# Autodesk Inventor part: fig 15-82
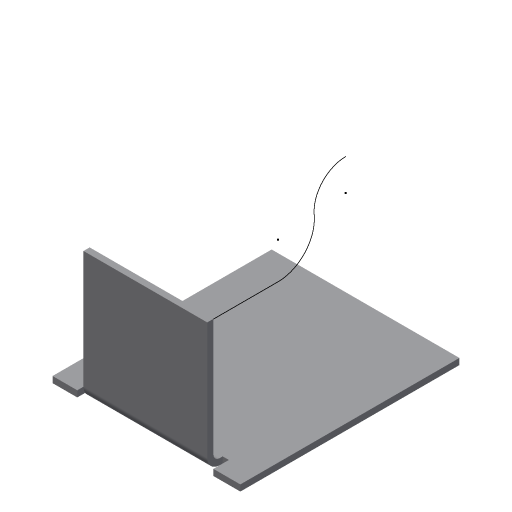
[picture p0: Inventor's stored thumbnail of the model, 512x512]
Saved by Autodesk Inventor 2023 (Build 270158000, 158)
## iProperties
Created: 2002-04
Part Number: fig 15-82
Document SubType Name: Sheet Metal
Density: 1 g/cm^3
Sheet Metal Rule: Default
Material: Generic
Appearance: Default
Control State: 0
Master: False
Checked Out: False
Shininess: 77.0
Angle Display Precision: 2
Document Length Units: 11269
Document Angle Units: 11279
Document Time Units: 11290
Document Mass Units: 11283
Document Length Units Precision: 3
Document Angle Units Precision: 2
Compacted: True
Density: 0.0
Volumn: 0.0
Area: 0.0
PropertySet Name: Model Information
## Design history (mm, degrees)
node "Face1"
  sketch "Sketch1"
    geometry: L1 (-24.824, 17.882)-(5.529, 17.882); L2 (5.529, 17.882)-(5.529, -17.529); L3 (5.529, -17.529)-(-24.824, -17.529); L4 (-24.824, -17.529)-(-24.824, 17.882)
    constraints: 8 end point, 2 parallel, 1 horizontal, 1 perpendicular
node "Flange1"
sketch "Sketch5"
  geometry: L1 (0, 1)-(0, 11.431); A1 r 5.855 centre (-5.855, 11.431) between (0, 11.431) and (-6.422, 17.259); A2 r 5.142 centre (-6.92, 22.376) between (-12.062, 22.382) and (-6.422, 17.259)
  constraints: 4 point on circle, 2 centre point, 2 end point, 2 tangent
body "Solid1"
face "Plate1" dims "d33" = 1 (= Thickness)
sketch "Sketch3"
  geometry: L1 (25.353, 0)-(5.353, 0); L2 (5.353, 0)-(5.353, 20); L3 (5.353, 20)-(25.353, 20); L4 (25.353, 20)-(25.353, 0)
  constraints: 8 end point
face "Plate3" dims "d5" = 20, "d6" = 90 deg, "d7" = 1 (= BendRadius), "d11" = 5, "d12" = 20, "d33" = 1 (= Thickness), "MinimumRemnant" = 2 (= 2 x Thickness), "BendReliefWidth" = 1 (= Thickness)
bend "Bend2" dims "d5" = 20, "d6" = 90 deg, "d7" = 1 (= BendRadius), "d21" = 1 (= BendReliefWidth), "d22" = 0.5 (= BendReliefDepth), "d23" = 2 (= MinimumRemnant), "d33" = 1 (= Thickness), "SeamGap" = 0.01, "MinimumRemnant" = 2 (= 2 x Thickness), "BendReliefWidth" = 1 (= Thickness), "TransitionRadius" = 1 (= BendRadius)
other parameters: "Thickness" = 1, "BendRadius" = 1 (= Thickness), "BendReliefDepth" = 0.5 (= 0.5 x Thickness), "CornerReliefSize" = 4 (= 4 x Thickness), "d0" = 1 (= BendRadius), "d4" = 1 (= BendRadius), "JacobiRadiusSize" = 1 (= Thickness), "GapSize" = 1 (= Thickness)
